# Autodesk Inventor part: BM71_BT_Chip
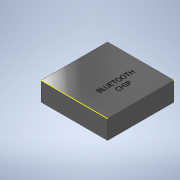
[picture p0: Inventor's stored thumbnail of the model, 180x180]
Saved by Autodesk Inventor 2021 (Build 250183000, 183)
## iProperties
Created: 2021-02
Part Number: BM71_BT_Chip
Material: Generic
Document SubType Name: Modeling
Designer: callu
Density: 1 g/cm^3
Appearance: Default
Author: callu
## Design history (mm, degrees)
sketch "Sketch6"
  geometry: L1 (0, 0)-(3.5, 0); L2 (3.5, 0)-(3.5, -3.5); L3 (3.5, -3.5)-(0, -3.5); L4 (0, -3.5)-(0, 0)
  constraints: 8 end point, 2 parallel, 1 horizontal, 1 perpendicular
  dimensions: "d19" = 3.5 distance of L2.end L3.end; "d20" = 3.5 distance of L1.end L2.end
extrude "Extrusion4" new body sketch "Sketch6" distance "d21" = 1; taper "d22" = 0 deg
sketch "Sketch7"
  geometry: L1 (-3.5, 1.618)-(0.325, 1.618); L2 (0.325, 1.618)-(0.325, 0.275); L3 (0.325, 0.275)-(-3.5, 0.275); L4 (-3.5, 0.275)-(-3.5, 1.618); L5 (-3.5, 3.5)-(-3.5, 0) reference; 1 further point
  constraints: 2 other
  dimensions: "d23" = 0 distance between parallel lines of L5 L4
body "Solid2"
